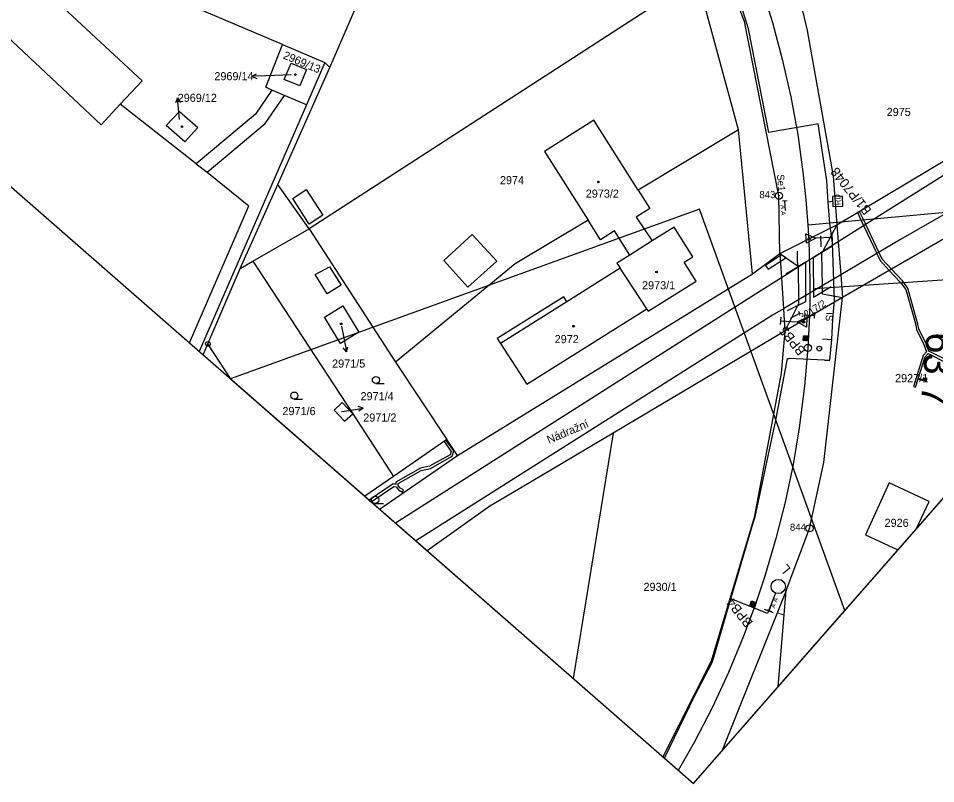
# Model space of a CAD drawing. Extents: x -620475 to -619963, y -1123010 to -1122510.
# Drawn here: x -620300.1 to -620107.7, y -1123010.1 to -1122849.6 of the extents above; entities that cross this region are included whole.
import ezdxf

# ---------------------------------------------------------------- set-up
doc = ezdxf.new("R2010")
doc.units = 0
for name, color, linetype in [('HranDP', 7, 'Continuous'), ('Hranice parcel', 7, 'Continuous'), ('Parcelní čísla', 7, 'Continuous'), ('Pop  PČ popisy', 7, 'Continuous'), ('Rámečky', 7, 'Continuous'), ('Rámečky-tisk', 7, 'Continuous'), ('Vnitřní kresba', 7, 'Continuous'), ('Vrstva 1', 7, 'Continuous'), ('Vrstva 19', 7, 'Continuous'), ('Vrstva 2', 7, 'Continuous'), ('Vrstva 3', 7, 'Continuous'), ('Vrstva 4', 7, 'Continuous'), ('Vrstva 51', 7, 'Continuous'), ('Vrstva 6', 7, 'Continuous'), ('Vrstva 7', 7, 'Continuous'), ('Věcná břemena k části', 7, 'Continuous'), ('Značky bodu BP', 7, 'Continuous'), ('Značky budov', 7, 'Continuous'), ('Značky kultur', 7, 'Continuous')]:
    doc.layers.add(name, color=color, linetype=linetype)

msp = doc.modelspace()

# ---------------------------------------------------------------- linework, layer by layer
at = {"layer": 'HranDP'}
for points in [[(-620143.18, -1122816.17), (-620134.66, -1122852.11), (-620129.18, -1122882.66), (-620128.4, -1122892.9)], [(-620140.38, -1122898.92), (-620140.56, -1122886.8), (-620147.76, -1122850.22), (-620152.84, -1122837.4)], [(-620128.4, -1122892.9), (-620131.42, -1122898.55), (-620131.63, -1122898.95), (-620131.51, -1122905.69)], [(-620140.38, -1122898.92), (-620136.53, -1122901.57), (-620136.53, -1122901.79), (-620136.48, -1122908.63), (-620136.47, -1122909.48), (-620139.31, -1122915.18)], [(-620131.51, -1122905.69), (-620131.48, -1122907.34), (-620127.22, -1122908.12)], [(-620139.01, -1122969.61), (-620134.15, -1122956.58), (-620131.17, -1122942.74), (-620127.22, -1122908.12)], [(-620139.31, -1122915.18), (-620140.08, -1122924.01), (-620145.74, -1122954.29), (-620154.8, -1122984.44), (-620164.93, -1123004.51)], [(-620139.01, -1122969.61), (-620152.54, -1123003.33)]]:
    msp.add_lwpolyline(points, dxfattribs=at)
at = {"layer": 'Hranice parcel'}
for p, q in [((-620244.68, -1122855.06), (-620280.92, -1122839.64)), ((-620244.68, -1122855.06), (-620235.77, -1122858.86)), ((-620234.78, -1122859.86), (-620235.77, -1122858.86)), ((-620250.91, -1122900.53), (-620239.08, -1122893.74)), ((-620239.08, -1122893.74), (-620220.99, -1122921.7)), ((-620140.38, -1122898.92), (-620128.4, -1122892.9)), ((-620105.32, -1122895.5), (-620127.22, -1122908.12)), ((-620146.13, -1122903.17), (-620140.38, -1122898.92)), ((-620253.53, -1122902.03), (-620250.91, -1122900.53)), ((-620260.32, -1122917.88), (-620253.53, -1122902.03)), ((-620208, -1122941.31), (-620146.13, -1122903.17)), ((-620127.22, -1122908.12), (-620139.31, -1122915.18)), ((-620139.31, -1122915.18), (-620175.35, -1122936.6)), ((-620261.31, -1122920.2), (-620260.32, -1122917.88)), ((-620255.45, -1122925.33), (-620260.32, -1122917.88)), ((-620220.99, -1122921.7), (-620210.21, -1122937.96)), ((-620210.21, -1122937.96), (-620221.39, -1122945.68)), ((-620208, -1122941.31), (-620210.21, -1122937.96)), ((-620224.32, -1122952.56), (-620208, -1122941.31)), ((-620221.39, -1122945.68), (-620227.42, -1122949.84)), ((-620201.16, -1122951.94), (-620214.32, -1122961.31)), ((-620140.71, -1122989.82), (-620139.01, -1122969.61))]:
    msp.add_line(p, q, dxfattribs=at)
for points in [[(-620234.78, -1122859.86), (-620228.39, -1122845.14), (-620201.6, -1122784.9)], [(-620143.18, -1122816.17), (-620134.66, -1122852.11), (-620129.18, -1122882.66), (-620128.4, -1122892.9)], [(-620152.84, -1122837.4), (-620157.72, -1122840.99), (-620239.08, -1122893.74)], [(-620140.38, -1122898.92), (-620140.56, -1122886.8), (-620147.76, -1122850.22), (-620152.84, -1122837.4)], [(-620301.53, -1122845.3), (-620297.45, -1122840.93), (-620274.13, -1122862.72)], [(-620274.13, -1122862.72), (-620278.69, -1122867.6), (-620282.72, -1122871.91), (-620306.02, -1122850.12)], [(-620235.77, -1122858.86), (-620239.62, -1122867.69), (-620244.23, -1122865.77), (-620246.9, -1122864.61), (-620248.18, -1122864.05), (-620244.68, -1122855.06)], [(-620128.4, -1122892.9), (-620078.79, -1122863.28), (-620080.86, -1122856.55)], [(-620239.62, -1122860.31), (-620241.03, -1122863.75), (-620244.32, -1122862.42), (-620242.88, -1122858.98), (-620239.62, -1122860.31)], [(-620253.53, -1122902.03), (-620245.67, -1122884.47), (-620234.78, -1122859.86)], [(-620262.45, -1122872.51), (-620265.17, -1122875.49), (-620269.05, -1122872.04), (-620266.28, -1122869.15), (-620262.45, -1122872.51)], [(-620170.07, -1122885.6), (-620179.4, -1122870.92), (-620189.75, -1122877.5), (-620180.6, -1122891.9)], [(-620146.13, -1122903.17), (-620149.02, -1122872.99), (-620170.07, -1122885.6)], [(-620170.07, -1122885.6), (-620167.62, -1122889.46), (-620170.53, -1122891.31), (-620167.12, -1122896.26), (-620171.85, -1122899.25), (-620175.05, -1122894.19), (-620177.97, -1122896.04), (-620180.6, -1122891.9)], [(-620180.6, -1122891.9), (-620195.9, -1122901.07), (-620220.99, -1122921.7)], [(-620128.4, -1122892.9), (-620131.42, -1122898.55), (-620131.63, -1122898.95), (-620131.51, -1122905.69)], [(-620140.38, -1122898.92), (-620136.53, -1122901.57), (-620136.53, -1122901.79), (-620136.48, -1122908.63), (-620136.47, -1122909.48), (-620139.31, -1122915.18)], [(-620250.91, -1122900.53), (-620229.95, -1122932.57), (-620221.39, -1122945.68)], [(-620198.98, -1122917.79), (-620193.45, -1122926.35), (-620168.27, -1122910.5), (-620173.85, -1122901.99), (-620185.06, -1122909.04), (-620185.7, -1122908.03), (-620199.62, -1122916.78), (-620198.98, -1122917.79)], [(-620131.51, -1122905.69), (-620131.48, -1122907.34), (-620127.22, -1122908.12)], [(-620139.01, -1122969.61), (-620134.15, -1122956.58), (-620131.17, -1122942.74), (-620127.22, -1122908.12)], [(-620228.65, -1122915.4), (-620232.52, -1122917.77), (-620235.88, -1122912.25), (-620231.99, -1122909.89), (-620228.65, -1122915.4)], [(-620139.31, -1122915.18), (-620140.08, -1122924.01), (-620145.74, -1122954.29), (-620154.8, -1122984.44), (-620164.93, -1123004.51)], [(-620229.95, -1122932.57), (-620232.13, -1122930.14), (-620233.86, -1122931.77)], [(-620233.86, -1122931.77), (-620231.67, -1122934.08), (-620229.95, -1122932.57)], [(-620175.35, -1122936.6), (-620194.44, -1122947.94), (-620201.16, -1122951.94)], [(-620175.35, -1122936.6), (-620183.73, -1122988.07)], [(-620111.68, -1122956.63), (-620109.02, -1122950.94), (-620117.41, -1122947.01), (-620122.42, -1122957.94)], [(-620122.42, -1122957.94), (-620115.6, -1122961.11)], [(-620139.01, -1122969.61), (-620152.54, -1123003.33)]]:
    msp.add_lwpolyline(points, dxfattribs=at)
at = {"layer": 'Pop  PČ popisy'}
for p, q in [((-620251.09, -1122861.73), (-620250.11, -1122861.19)), ((-620248.09, -1122861.62), (-620251.09, -1122861.73)), ((-620251.09, -1122861.73), (-620250.07, -1122862.19)), ((-620242.88, -1122861.46), (-620248.09, -1122861.62)), ((-620266.68, -1122866.25), (-620267.09, -1122867.29)), ((-620266.42, -1122869.24), (-620266.68, -1122866.25)), ((-620266.68, -1122866.25), (-620266.09, -1122867.2)), ((-620266.29, -1122870.78), (-620266.42, -1122869.24)), ((-620232.3, -1122914.19), (-620231.83, -1122916.62)), ((-620231.83, -1122916.62), (-620231.26, -1122919.57)), ((-620231.26, -1122919.57), (-620231.94, -1122918.68)), ((-620231.26, -1122919.57), (-620230.96, -1122918.49)), ((-620232.28, -1122932.09), (-620230.7, -1122931.83)), ((-620230.7, -1122931.83), (-620227.74, -1122931.36)), ((-620227.74, -1122931.36), (-620228.8, -1122931.02)), ((-620227.74, -1122931.36), (-620228.65, -1122932.01))]:
    msp.add_line(p, q, dxfattribs=at)
at = {"layer": 'Rámečky'}
msp.add_line((-620158.49, -1123010.14), (-619962.95, -1122786.6), dxfattribs=at)
for points in [[(-620279.07, -1122510.07), (-620474.61, -1122733.62), (-620158.49, -1123010.14)], [(-620126.7, -1122973.8), (-620157.19, -1122889.6), (-620255.57, -1122925.22)], [(-620255.57, -1122925.22), (-620158.49, -1123010.14), (-620126.7, -1122973.8)]]:
    msp.add_lwpolyline(points, dxfattribs=at)
at = {"layer": 'Rámečky-tisk'}
for points in [[(-620279.07, -1122510.07), (-620474.61, -1122733.62), (-620158.49, -1123010.14)], [(-620158.49, -1123010.14), (-619962.95, -1122786.6), (-620279.07, -1122510.07)], [(-620126.7, -1122973.8), (-620157.19, -1122889.6), (-620255.57, -1122925.22)], [(-620255.57, -1122925.22), (-620158.49, -1123010.14), (-620126.7, -1122973.8)]]:
    msp.add_lwpolyline(points, dxfattribs=at)
at = {"layer": 'Vnitřní kresba'}
for p, q in [((-620149.02, -1122872.99), (-620157.72, -1122840.99)), ((-620246.9, -1122864.61), (-620250.37, -1122869.68)), ((-620248.3, -1122871.67), (-620244.23, -1122865.77)), ((-620080.37, -1122866.39), (-620119.37, -1122890.92)), ((-620262.79, -1122880.12), (-620278.69, -1122867.6)), ((-620239.62, -1122867.69), (-620262.18, -1122919.44)), ((-620250.37, -1122869.68), (-620262.79, -1122880.12)), ((-620260.48, -1122881.85), (-620248.3, -1122871.67)), ((-620262.79, -1122880.12), (-620260.48, -1122881.85)), ((-620260.48, -1122881.85), (-620251.76, -1122888.93)), ((-620239.08, -1122893.74), (-620245.67, -1122884.47)), ((-620242.49, -1122887.38), (-620239.68, -1122885.51)), ((-620239.68, -1122885.51), (-620236.19, -1122890.86)), ((-620239.05, -1122892.73), (-620242.49, -1122887.38)), ((-620100.87, -1122887.82), (-620115.07, -1122895.95)), ((-620264.19, -1122917.69), (-620251.76, -1122888.93)), ((-620236.19, -1122890.86), (-620239.05, -1122892.73)), ((-620119.37, -1122890.92), (-620128.12, -1122896.46)), ((-620162.51, -1122893.37), (-620167.12, -1122896.26)), ((-620158.59, -1122899.61), (-620162.51, -1122893.37)), ((-620128.4, -1122892.9), (-620128.12, -1122896.46)), ((-620210.87, -1122900.4), (-620204.92, -1122894.91)), ((-620204.92, -1122894.91), (-620199.73, -1122900.55)), ((-620128.12, -1122896.46), (-620131.42, -1122898.55)), ((-620128.12, -1122896.46), (-620127.59, -1122903.37)), ((-620115.07, -1122895.95), (-620127.59, -1122903.37)), ((-620171.85, -1122899.25), (-620174.52, -1122900.92)), ((-620160.44, -1122900.76), (-620158.59, -1122899.61)), ((-620140.38, -1122898.92), (-620140.04, -1122904.01)), ((-620131.42, -1122898.55), (-620136.53, -1122901.79)), ((-620205.8, -1122906), (-620210.87, -1122900.4)), ((-620199.73, -1122900.55), (-620205.8, -1122906)), ((-620174.52, -1122900.92), (-620173.85, -1122901.99)), ((-620157.94, -1122904.69), (-620160.44, -1122900.76)), ((-620237.8, -1122903.34), (-620234.8, -1122901.69)), ((-620235.3, -1122907.35), (-620237.8, -1122903.34)), ((-620234.8, -1122901.69), (-620232.38, -1122905.55)), ((-620136.53, -1122901.79), (-620140.04, -1122904.01)), ((-620127.59, -1122903.37), (-620131.51, -1122905.69)), ((-620127.59, -1122903.37), (-620127.22, -1122908.12)), ((-620167.95, -1122911), (-620157.94, -1122904.69)), ((-620140.04, -1122904.01), (-620144.7, -1122906.96)), ((-620140.04, -1122904.01), (-620139.62, -1122910.5)), ((-620232.38, -1122905.55), (-620235.3, -1122907.35)), ((-620144.7, -1122906.96), (-620220.97, -1122955.49)), ((-620131.51, -1122905.69), (-620136.48, -1122908.63)), ((-620185.06, -1122909.04), (-620198.98, -1122917.79)), ((-620136.48, -1122908.63), (-620139.62, -1122910.5)), ((-620168.27, -1122910.5), (-620167.95, -1122911)), ((-620139.62, -1122910.5), (-620141.9, -1122911.85)), ((-620139.62, -1122910.5), (-620139.31, -1122915.18)), ((-620141.9, -1122911.85), (-620216.73, -1122959.2))]:
    msp.add_line(p, q, dxfattribs=at)
at = {"layer": 'Vrstva 1'}
for p, q in [((-620133.37, -1122871.92), (-620140.39, -1122873.11)), ((-620129.27, -1122888.02), (-620130.22, -1122888.11)), ((-620128.92, -1122908.69), (-620129.3, -1122896.72)), ((-620131.45, -1122916.84), (-620129.47, -1122916.94)), ((-620130.97, -1122921.27), (-620138.43, -1122920.94)), ((-620148.83, -1122972.09), (-620150.63, -1122971.37)), ((-620142.94, -1122974.46), (-620148.83, -1122972.09)), ((-620142.71, -1122973.89), (-620142.94, -1122974.46))]:
    msp.add_line(p, q, dxfattribs=at)
for points in [[(-620140.39, -1122873.11), (-620142.65, -1122873.56), (-620146.97, -1122851.79), (-620148.85, -1122845.74), (-620151.28, -1122839.45)], [(-620144.33, -1122842.64), (-620141.9, -1122850.48), (-620139.85, -1122858.17), (-620138.09, -1122866.06), (-620136.62, -1122873.96), (-620135.51, -1122881.84), (-620134.9, -1122887.57), (-620134.42, -1122893.91), (-620134.34, -1122895.32), (-620134.21, -1122898.3), (-620134.18, -1122899.02), (-620134.08, -1122904.54), (-620134.09, -1122909), (-620134.14, -1122911.92), (-620134.48, -1122918.72), (-620135.16, -1122926.76), (-620136.29, -1122935.46), (-620137.6, -1122943.19), (-620139.25, -1122951.1), (-620141.18, -1122958.74), (-620143.49, -1122966.59), (-620145.52, -1122972.66), (-620147.96, -1122979.17), (-620151.13, -1122986.8), (-620154.5, -1122994.08), (-620158.35, -1123001.53), (-620161.67, -1123007.37)], [(-620130.22, -1122888.11), (-620130.54, -1122883.68), (-620132.31, -1122871.72), (-620133.37, -1122871.92)], [(-620129.3, -1122896.72), (-620129.88, -1122892.6), (-620129.88, -1122892.6), (-620130.22, -1122888.11)], [(-620129.47, -1122916.94), (-620129.26, -1122912.72), (-620129.26, -1122912.72), (-620128.92, -1122908.69)], [(-620130.97, -1122921.27), (-620129.91, -1122921.31), (-620129.47, -1122916.94)], [(-620150.63, -1122971.37), (-620145.98, -1122955.43), (-620145.54, -1122954.13), (-620141.24, -1122933.85), (-620138.78, -1122920.93), (-620138.43, -1122920.94)], [(-620164.58, -1123004.82), (-620158.18, -1122991.64), (-620154.53, -1122984.74), (-620154, -1122982.93), (-620152.3, -1122977.09), (-620150.63, -1122971.37)]]:
    msp.add_lwpolyline(points, dxfattribs=at)
at = {"layer": 'Vrstva 19'}
for p, q in [((-620074.7, -1122887.47), (-620134.45, -1122892.95)), ((-620131.87, -1122895.21), (-620131.8, -1122897.49))]:
    msp.add_line(p, q, dxfattribs=at)
for points in [[(-620139.12, -1122903.19), (-620136.58, -1122901.68), (-620136.67, -1122899.95), (-620136.66, -1122899.92), (-620136.68, -1122898.42)], [(-620136.48, -1122911.01), (-620136.23, -1122911.48), (-620138.22, -1122912.56)]]:
    msp.add_lwpolyline(points, dxfattribs=at)
at = {"layer": 'Vrstva 2'}
for p, q in [((-620135.46, -1122917.02), (-620135.28, -1122917.21)), ((-620135.45, -1122916.83), (-620135.1, -1122917.22)), ((-620135.44, -1122916.46), (-620134.73, -1122917.24)), ((-620135.44, -1122916.65), (-620134.91, -1122917.23)), ((-620135.43, -1122916.28), (-620134.54, -1122917.24)), ((-620135.36, -1122916.16), (-620134.42, -1122917.19)), ((-620135.18, -1122916.17), (-620134.41, -1122917)), ((-620134.99, -1122916.17), (-620134.4, -1122916.81)), ((-620134.8, -1122916.18), (-620134.39, -1122916.63)), ((-620134.62, -1122916.19), (-620134.38, -1122916.44)), ((-620134.43, -1122916.2), (-620134.38, -1122916.26)), ((-620141.25, -1122970.17), (-620142.71, -1122973.89)), ((-620146.62, -1122972.63), (-620146.51, -1122972.86)), ((-620146.56, -1122972.45), (-620146.34, -1122972.92)), ((-620146.5, -1122972.28), (-620146.16, -1122972.98)), ((-620146.44, -1122972.1), (-620145.99, -1122973.05)), ((-620146.38, -1122971.93), (-620145.81, -1122973.11)), ((-620146.28, -1122971.83), (-620145.68, -1122973.09)), ((-620146.1, -1122971.89), (-620145.61, -1122972.92)), ((-620145.93, -1122971.95), (-620145.55, -1122972.74)), ((-620145.75, -1122972.02), (-620145.49, -1122972.57)), ((-620145.58, -1122972.08), (-620145.43, -1122972.39)), ((-620145.4, -1122972.14), (-620145.37, -1122972.22)), ((-620143.65, -1122973.53), (-620141.78, -1122974.26))]:
    msp.add_line(p, q, dxfattribs=at)
for points in [[(-620127.12, -1122888.96), (-620127.22, -1122886.86), (-620129.32, -1122886.97), (-620129.22, -1122889.07)], [(-620134.37, -1122916.2), (-620134.42, -1122917.25), (-620135.47, -1122917.2), (-620135.42, -1122916.16)], [(-620134.37, -1122916.2), (-620134.42, -1122917.25), (-620135.47, -1122917.2), (-620135.42, -1122916.16)], [(-620145.35, -1122972.16), (-620145.7, -1122973.15), (-620146.69, -1122972.8), (-620146.34, -1122971.81)], [(-620145.35, -1122972.16), (-620145.7, -1122973.15), (-620146.69, -1122972.8), (-620146.34, -1122971.81)]]:
    msp.add_lwpolyline(points, close=True, dxfattribs=at)
msp.add_circle((-620140.7, -1122968.78), 1.5, dxfattribs=at)
at = {"layer": 'Vrstva 3'}
for p, q in [((-620135.12, -1122911.37), (-620135.17, -1122912.37)), ((-620133.14, -1122911.97), (-620135.14, -1122911.87)), ((-620133.12, -1122911.47), (-620133.17, -1122912.47))]:
    msp.add_line(p, q, dxfattribs=at)
at = {"layer": 'Vrstva 4'}
for p, q in [((-620134.02, -1122895.95), (-620134.37, -1122895.61)), ((-620129.33, -1122896.31), (-620129.39, -1122894.76)), ((-620133.06, -1122906.27), (-620073.2, -1122902.2)), ((-620140.19, -1122912.29), (-620140.28, -1122913.84)), ((-620135.56, -1122913.09), (-620135.23, -1122913.46))]:
    msp.add_line(p, q, dxfattribs=at)
for points in [[(-620129.36, -1122895.53), (-620132.83, -1122895.69), (-620134.79, -1122896.76), (-620134.89, -1122894.77), (-620132.83, -1122895.69)], [(-620134.18, -1122899.02), (-620134.08, -1122904.54), (-620134.09, -1122909)], [(-620140.23, -1122913.07), (-620136.76, -1122913.24), (-620134.71, -1122912.35), (-620134.8, -1122914.35), (-620136.76, -1122913.24)]]:
    msp.add_lwpolyline(points, dxfattribs=at)
for centre in [(-620134.19, -1122895.78), (-620135.4, -1122913.28)]:
    msp.add_circle(centre, 0.248, dxfattribs=at)
at = {"layer": 'Vrstva 51'}
for points in [[(-620129.62, -1122897.5), (-620133.36, -1122899.81), (-620133.29, -1122908.06), (-620129.57, -1122905.87)], [(-620138.79, -1122910.87), (-620134.88, -1122909), (-620134.94, -1122900.75), (-620136.58, -1122901.68)]]:
    msp.add_lwpolyline(points, dxfattribs=at)
at = {"layer": 'Vrstva 6'}
for p, q in [((-620138.81, -1122887.87), (-620139.8, -1122887.95)), ((-620139.16, -1122889.88), (-620139.31, -1122887.91)), ((-620141.96, -1122971.97), (-620142.59, -1122973.84)), ((-620143.06, -1122973.69), (-620142.12, -1122974))]:
    msp.add_line(p, q, dxfattribs=at)
at = {"layer": 'Vrstva 7'}
msp.add_line((-620132.07, -1122918.82), (-620132.08, -1122918.92), dxfattribs=at)
for centre, radius in [((-620134.48, -1122918.72), 0.75), ((-620132.08, -1122918.87), 0.5)]:
    msp.add_circle(centre, radius, dxfattribs=at)
at = {"layer": 'Věcná břemena k části'}
msp.add_line((-620226.5, -1122950.65), (-620226.11, -1122951), dxfattribs=at)
for points in [[(-620116.97, -1122902.21), (-620118.88, -1122900.07), (-620122.96, -1122891.51), (-620123.66, -1122890.07), (-620124.09, -1122890.33), (-620123.42, -1122891.73), (-620119.3, -1122900.35), (-620117.41, -1122902.47)], [(-620139.12, -1122899.79), (-620140.01, -1122899.18), (-620143.39, -1122901.4), (-620142.84, -1122902.23)]]:
    msp.add_lwpolyline(points, close=True, dxfattribs=at)
for points in [[(-620105.34, -1122921.32), (-620109.13, -1122919.41), (-620109.7, -1122917.84), (-620111.19, -1122914.71), (-620111.39, -1122913.73), (-620113.5, -1122906.22), (-620114.67, -1122904.66), (-620116.97, -1122902.21), (-620117.41, -1122902.47), (-620115.05, -1122904.98), (-620113.96, -1122906.44), (-620111.87, -1122913.85), (-620111.67, -1122914.87), (-620110.16, -1122918.04), (-620109.62, -1122919.54), (-620110.32, -1122920.32), (-620112.35, -1122926.85), (-620111.88, -1122926.99), (-620109.88, -1122920.58), (-620109.27, -1122919.9), (-620105.58, -1122921.76)], [(-620226.11, -1122951), (-620221.34, -1122947.77), (-620220.85, -1122947.88), (-620220.38, -1122948.48), (-620219.54, -1122948.96), (-620219.3, -1122948.52), (-620220.04, -1122948.1), (-620220.45, -1122947.58), (-620220.43, -1122947.18), (-620215.58, -1122944.45), (-620213.67, -1122944.01), (-620209.12, -1122941.46), (-620208.72, -1122940.34), (-620210.39, -1122938.08), (-620210.8, -1122938.37), (-620209.28, -1122940.42), (-620209.52, -1122941.12), (-620213.85, -1122943.53), (-620215.76, -1122943.97), (-620220.91, -1122946.88), (-620220.94, -1122947.35), (-620221.44, -1122947.23), (-620226.5, -1122950.65)]]:
    msp.add_lwpolyline(points, dxfattribs=at)
at = {"layer": 'Značky bodu BP'}
for centre, radius in [((-620140.56, -1122886.8), 0.75), ((-620140.56, -1122886.8), 0.03), ((-620260.32, -1122917.88), 0.5), ((-620260.32, -1122917.88), 0.0303), ((-620134.15, -1122956.58), 0.75), ((-620134.15, -1122956.58), 0.03)]:
    msp.add_circle(centre, radius, dxfattribs=at)
at = {"layer": 'Značky budov'}
for centre in [(-620241.97, -1122861.36), (-620265.74, -1122872.31), (-620178.44, -1122883.88), (-620166.23, -1122902.81), (-620232.36, -1122913.67), (-620183.64, -1122914.16)]:
    msp.add_circle(centre, 0.175, dxfattribs=at)
at = {"layer": 'Značky kultur'}
for p, q in [((-620225.08, -1122926.21), (-620223.33, -1122926.21)), ((-620242.2, -1122929.48), (-620240.45, -1122929.48)), ((-620225.25, -1122951.34), (-620223.5, -1122951.34))]:
    msp.add_line(p, q, dxfattribs=at)
for centre in [(-620225.08, -1122925.46), (-620242.2, -1122928.73), (-620225.25, -1122950.59)]:
    msp.add_circle(centre, 0.75, dxfattribs=at)

# ---------------------------------------------------------------- texts
at = {"layer": 'Parcelní čísla'}
for s, height, rotation, p in [('2969/13', 1.7, 337, (-620244.7, -1122857.94)), ('3217/2', 1.5, 32, (-620135.73, -1122913.04))]:
    msp.add_text(s, height=height, rotation=rotation, dxfattribs=at).set_placement(p)
for s, p in [('2969/14', (-620258.97, -1122862.56)), ('2969/12', (-620266.66, -1122867.1)), ('2975', (-620117.96, -1122870.06)), ('2974', (-620199.07, -1122884.37)), ('2973/2', (-620181.07, -1122887.2)), ('2973/1', (-620169.27, -1122906.43)), ('2972', (-620187.59, -1122917.72)), ('2971/5', (-620234.27, -1122922.85)), ('2927/1', (-620116.2, -1122925.91)), ('2971/4', (-620228.31, -1122929.7)), ('2971/6', (-620244.69, -1122932.82)), ('2971/2', (-620227.74, -1122934.18)), ('2926', (-620118.4, -1122956.27)), ('2930/1', (-620168.96, -1122969.7))]:
    msp.add_text(s, height=1.7, dxfattribs=at).set_placement(p)
at = {"layer": 'Pop  PČ popisy'}
msp.add_text('Nádražní', height=1.7, rotation=23, dxfattribs=at).set_placement((-620188.79, -1122938.87))
at = {"layer": 'Vrstva 2'}
msp.add_text('RD', height=1.2, rotation=93.0505, dxfattribs=at).set_placement((-620127.58, -1122888.74))
at = {"layer": 'Vrstva 3'}
for s, height, rotation, p in [('B1/P7048', 2, 128.542, (-620121.02, -1122889.81)), ('IS', 1.5, 267.1804, (-620130.68, -1122911.19)), ('BPB5', 2, 128.542, (-620134.84, -1122919.29)), ('L', 2, 128.542, (-620137.97, -1122965.09)), ('BPB4', 2, 128.542, (-620145.92, -1122976.33))]:
    msp.add_text(s, height=height, rotation=rotation, dxfattribs=at).set_placement(p)
at = {"layer": 'Vrstva 6'}
for s, height, rotation, p in [('Se1', 1.5, 274.313, (-620140.97, -1122882.35)), ('  A A ', 1, 274.313, (-620140.3, -1122887.98)), ('  A A ', 1, 71.5027, (-620141.64, -1122974.16)), ('L', 1.5, 251.5027, (-620140.85, -1122974.05))]:
    msp.add_text(s, height=height, rotation=rotation, dxfattribs=at).set_placement(p)
at = {"layer": 'Vrstva 7'}
msp.add_text('63,7', height=6, rotation=265.1213, dxfattribs=at).set_placement((-620109.54, -1122915.27))
at = {"layer": 'Značky bodu BP'}
for s, p in [('843', (-620144.66, -1122887.3)), ('844', (-620138.25, -1122957.08))]:
    msp.add_text(s, height=1.5, dxfattribs=at).set_placement(p)

doc.saveas('drawing.dxf')
